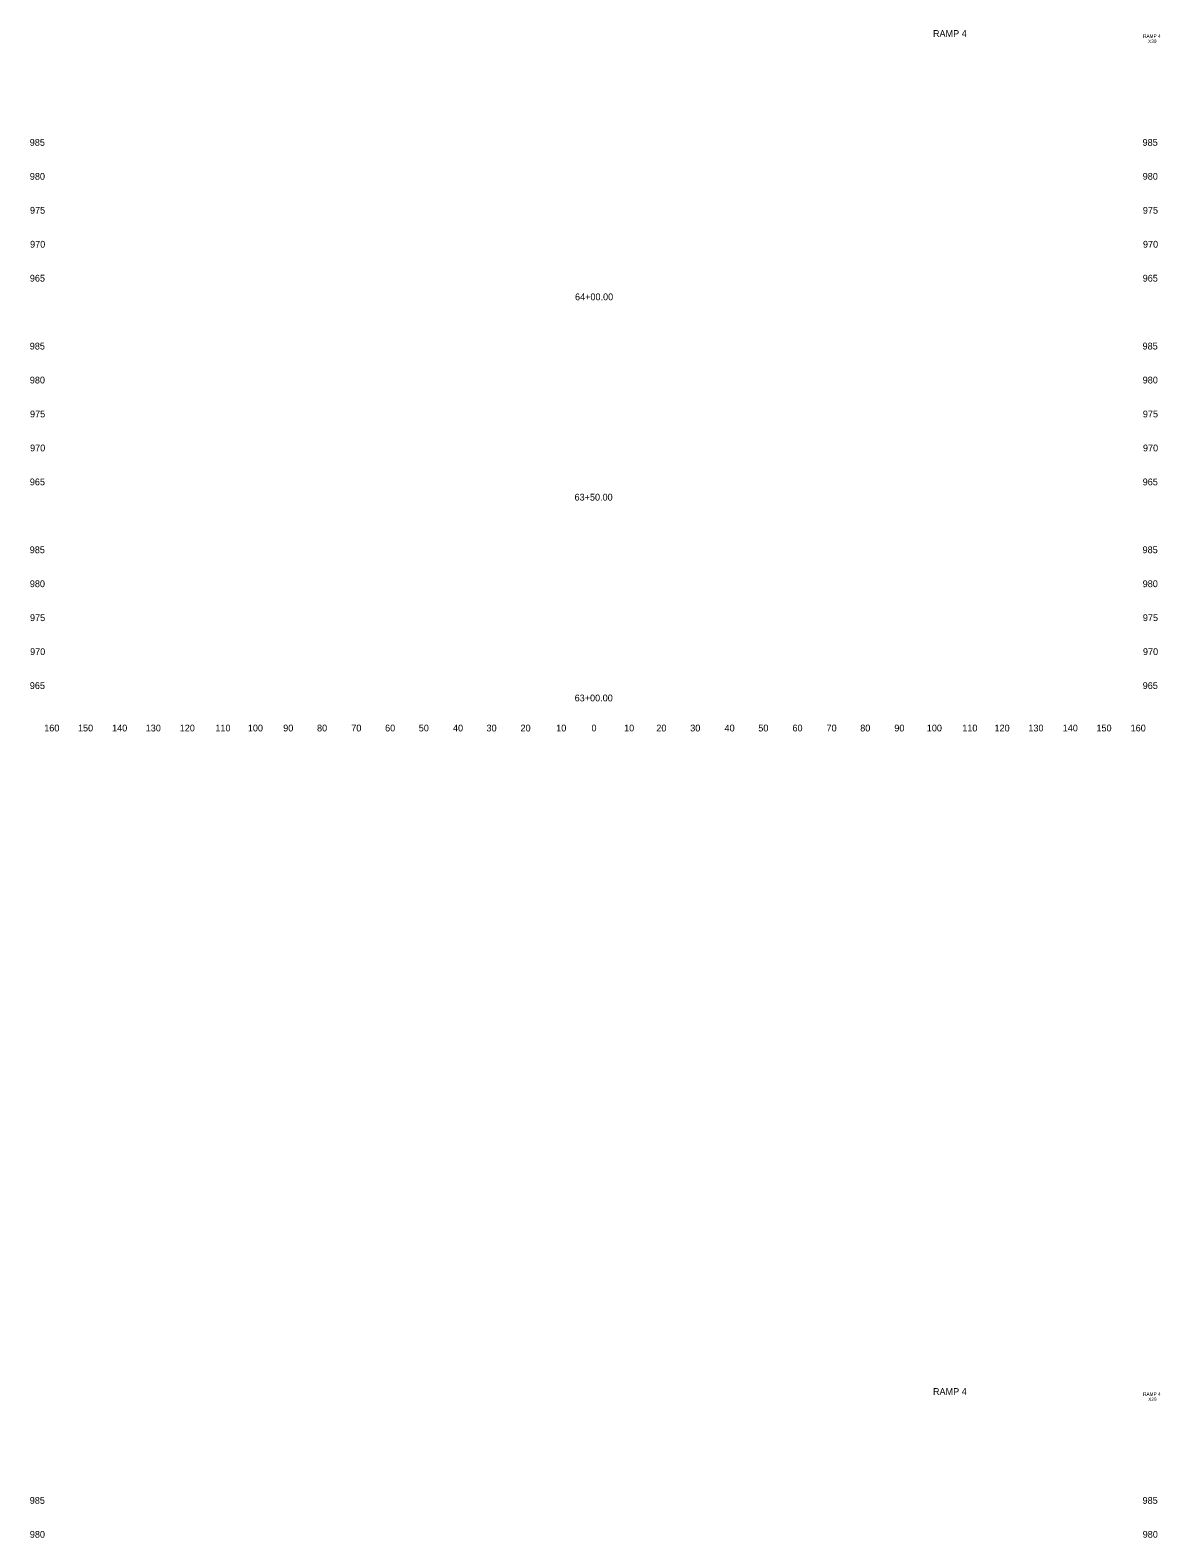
# Model space of a CAD drawing. Extents: x 4994 to 6872, y 4997 to 8804.
# Drawn here: x 6024 to 6356.7, y 8360 to 8804.1 of the extents above; entities that cross this region are included whole.
import ezdxf

# ---------------------------------------------------------------- set-up
doc = ezdxf.new("R2010")
doc.units = 0
for name, color, linetype in [('RD_SHT_ID', 7, 'Continuous'), ('RD_XS_TX_Offset', 7, 'Continuous'), ('RD_XS_TX_Station', 7, 'Continuous')]:
    doc.layers.add(name, color=color, linetype=linetype)

msp = doc.modelspace()

# ---------------------------------------------------------------- texts
at = {"layer": 'RD_SHT_ID'}
for s, height, p in [('RAMP 4', 2, (6289.88, 8802.06)), ('RAMP 4', 1, (6351.78, 8801.8)), ('X30', 1, (6353.25, 8800.3)), ('RAMP 4', 2, (6289.88, 8402.06)), ('RAMP 4', 1, (6351.78, 8401.8)), ('X29', 1, (6353.29, 8400.3))]:
    msp.add_text(s, height=height, dxfattribs=at).set_placement(p)
at = {"layer": 'RD_XS_TX_Offset'}
for s, p in [('985', (6023.83, 8770)), ('985', (6351.63, 8770)), ('980', (6023.86, 8760)), ('980', (6351.66, 8760)), ('975', (6023.91, 8750)), ('975', (6351.71, 8750)), ('970', (6023.94, 8740)), ('970', (6351.74, 8740)), ('965', (6023.86, 8730)), ('965', (6351.66, 8730)), ('985', (6023.83, 8710)), ('985', (6351.63, 8710)), ('980', (6023.86, 8700)), ('980', (6351.66, 8700)), ('975', (6023.91, 8690)), ('975', (6351.71, 8690)), ('970', (6023.94, 8680)), ('970', (6351.74, 8680)), ('965', (6023.86, 8670)), ('965', (6351.66, 8670)), ('985', (6023.83, 8650)), ('985', (6351.63, 8650)), ('980', (6023.86, 8640)), ('980', (6351.66, 8640)), ('975', (6023.91, 8630)), ('975', (6351.71, 8630)), ('970', (6023.94, 8620)), ('970', (6351.74, 8620)), ('965', (6023.86, 8610)), ('965', (6351.66, 8610)), ('160', (6028.1, 8597.5)), ('150', (6038.04, 8597.5)), ('140', (6048.1, 8597.5)), ('130', (6057.99, 8597.5)), ('120', (6068.01, 8597.5)), ('110', (6078.51, 8597.5)), ('100', (6088.07, 8597.5)), ('90', (6098.5, 8597.5)), ('80', (6108.46, 8597.5)), ('70', (6118.54, 8597.5)), ('60', (6128.5, 8597.5)), ('50', (6138.43, 8597.5)), ('40', (6148.5, 8597.5)), ('30', (6158.39, 8597.5)), ('20', (6168.4, 8597.5)), ('10', (6178.91, 8597.5)), ('0', (6189.3, 8597.5)), ('0', (6189.3, 8597.5)), ('10', (6198.91, 8597.5)), ('20', (6208.4, 8597.5)), ('30', (6218.39, 8597.5)), ('40', (6228.5, 8597.5)), ('50', (6238.43, 8597.5)), ('60', (6248.5, 8597.5)), ('70', (6258.54, 8597.5)), ('80', (6268.46, 8597.5)), ('90', (6278.5, 8597.5)), ('100', (6288.07, 8597.5)), ('110', (6298.51, 8597.5)), ('120', (6308.01, 8597.5)), ('130', (6317.99, 8597.5)), ('140', (6328.1, 8597.5)), ('150', (6338.04, 8597.5)), ('160', (6348.1, 8597.5)), ('985', (6023.83, 8370)), ('985', (6351.63, 8370)), ('980', (6023.86, 8360)), ('980', (6351.66, 8360))]:
    msp.add_text(s, height=2, dxfattribs=at).set_placement(p)
at = {"layer": 'RD_XS_TX_Station'}
for s, p in [('64+00.00', (6184.45, 8724.51)), ('63+50.00', (6184.31, 8665.5)), ('63+00.00', (6184.34, 8606.36))]:
    msp.add_text(s, height=2, dxfattribs=at).set_placement(p)

doc.saveas('drawing.dxf')
